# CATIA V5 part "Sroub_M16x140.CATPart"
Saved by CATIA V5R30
Part number: Sroub_M16x140
Definition: E 1200_16x140_3
Nomenclature: E 1200_16x140_3
Source: Unknown
Description: PART--DESC
Bounding box of the stored display mesh (mm): x -152 to -128, y -148.99 to -125.01, z -24.3 to 131.7
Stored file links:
  E:\Bakalarka\Model\Forma_v7\Sroub_M16x140.CATPart
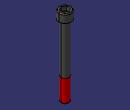
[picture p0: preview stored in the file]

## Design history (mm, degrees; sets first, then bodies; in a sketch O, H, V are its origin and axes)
Body1 "MANIFOLD_SOLID_BREP #3818" (main body)
  Solid1: solid without history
